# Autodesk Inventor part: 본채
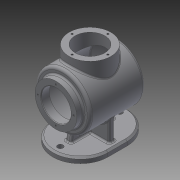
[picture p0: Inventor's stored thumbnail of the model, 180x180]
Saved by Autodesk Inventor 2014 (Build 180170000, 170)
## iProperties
Created: 2016-04
Part Number: 본채
Material: 일반
Document SubType Name: Modeling
Designer: basic
Density: 1 g/cm^3
Appearance: 기본값
Author: basic
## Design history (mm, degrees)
sketch "스케치6"
  geometry: L1 (-50, -67.5)-(50, -67.5); L2 (50, -67.5)-(50, 67.5); L3 (50, 67.5)-(-50, 67.5); L4 (-50, 67.5)-(-50, -67.5); L5 (-50, -67.5)-(50, 67.5); 2 further points
  constraints: 10 end point, 2 parallel, 1 coincident, 1 horizontal, 1 midpoint, 1 perpendicular
  dimensions: "d31" = 100 distance of L2.end L3.end; "d32" = 135 distance of L3.end L1.start
extrude "돌출3" join sketch "스케치6" distance "d34" = 10; taper "d35" = 0 deg
fillet "모깎기1" dims "d36" = 50
chamfer "모따기2" distance "d37" = 3; stored, may be unused: second distance "d38" = 2, angle "d39" = 45 deg
sketch "스케치7"
  geometry: L1 (64.5, 10)-(67.5, 7) reference; L2 (67.5, 7)-(67.5, 0) reference; L3 (67.5, 0)-(-67.5, 0) reference; L4 (-67.5, 0)-(-67.5, 7) reference; L5 (-67.5, 7)-(-64.5, 10) reference; L6 (-64.5, 10)-(64.5, 10) reference; L7 (-62, 79)-(60, 79); L8 (-62, 79)-(-62, 117); L9 (-62, 117)-(-50, 117); L10 (-50, 117)-(-50, 129); L11 (-62, 106)-(-47, 106); L12 (-47, 106)-(-47, 126); L13 (-47, 126)-(47.145, 126); L14 (-50, 129)-(49.087, 129); A1 r 120 centre (60, 79) between (-50, 126.958) and (-60, 79); A2 r 120 centre (-60, 79) between (60, 79) and (49.087, 129); A3 r 117 centre (-60, 79) between (57, 79) and (47.145, 126); 1 further point
  constraints: 16 end point, 6 point on circle, 4 point on line, 3 centre point, 3 parallel, 3 perpendicular, 1 coincident, 1 horizontal, 1 midpoint
  dimensions: "d40" = 122 distance of L7.end L7.start; "d41" = 79 distance between parallel lines of L3 L7; "d44" = 240 diameter of A1; "d46" = 3 radial gap between concentric circles of A2 A3; "d47" = 15 distance of L11.start L11.end; "d48" = 12 distance of L8.end L9.end; "d49" = 3 distance between parallel lines of L13 L14; "d50" = 50 distance between parallel lines of L7 L14; "d51" = 38 distance between parallel lines of L7 L9; "d52" = 27 distance between parallel lines of L7 L11; "d115" = 62 distance from line of point (0, 0) L8
revolve "회전3" sketch "스케치7" stored, may be unused: angle "d53" = 90 deg
sketch "스케치8" dims "d54" = 65
  geometry: L1 (0, 0)-(32.5, 0); C1 r 38 at (0, 0) reference; 2 further points
  constraints: 2 coincident, 2 end point, 1 horizontal, 1 horizontal alignment, 2 other
hole "구멍1" sketch "스케치8" at (32.5, 0) diameter "d55" = 3.242; stored, may be unused: countersink angle "d59" = 90 deg, drill point angle "d61" = 118 deg; dims "d56" = 8, "d57" = 4, "d58" = 2, "d60" = 10
node "작업 평면1"
sketch "스케치12"
  geometry: C1 r 5 at (0, -54); C2 r 5 at (0, 54); A1 r 47 centre (0, -17.5) between (-47, -17.5) and (47, -17.5) reference; A2 r 47 centre (0, 17.5) between (47, 17.5) and (-47, 17.5) reference; 1 further point
  constraints: 2 centre point, 2 vertical alignment
  dimensions: "d83" = 10 diameter of C1; "d84" = 10 diameter of C2; "d85" = 54 distance of point (0, 0) C1.centre; "d86" = 54 distance of C2.centre point (0, 0)
extrude "돌출6" cut sketch "스케치12" stored distance "d87" = 10; taper "d88" = 0 deg
fillet "모깎기2" dims "d89" = 2
fillet "모깎기3" dims "d90" = 5
chamfer "모따기3" distance "d91" = 1; stored, may be unused: second distance "d92" = 2, angle "d93" = 45 deg
sketch "스케치14"
  geometry: L1 (-50, 7)-(-47, 10) reference; L2 (-47, 10)-(47, 10) reference; L3 (47, 10)-(50, 7) reference; L4 (50, 7)-(50, 0) reference; L5 (50, 0)-(-50, 0) reference; L6 (-50, 0)-(-50, 7) reference; L7 (40, 10)-(40, 49); L8 (-40, 49)-(-40, 10); C1 r 47 at (0, 79) reference; A1 r 50 centre (0, 79) between (-40, 49) and (40, 49) reference; 1 further point
  constraints: 4 end point, 2 point on circle, 2 point on line, 1 parallel
  dimensions: "d99" = 40 distance from line of C1.centre L7; "d100" = 80 distance between parallel lines of L8 L7
extrude "돌출8" join sketch "스케치14" stored distance "d101" = 10; taper "d102" = 0 deg
sketch "스케치15"
  geometry: L1 (-51.026, 111.5)-(-52, 113.121) reference; L2 (-52, 113.121)-(-62, 113.121) reference; L3 (-62, 113.121)-(-62, 117) reference; L4 (-62, 117)-(-50, 117) reference; L5 (-50, 117)-(-50, 124) reference; L6 (-45, 129)-(45.83, 129) reference; L7 (45.83, 126)-(-45, 126) reference; L8 (-47, 124)-(-47, 106) reference; L9 (-47, 106)-(-61, 106) reference; L10 (-61, 106)-(-62, 107) reference; L11 (-62, 107)-(-62, 109.879) reference; L12 (-62, 109.879)-(-52, 109.879) reference; L13 (-52, 109.879)-(-51.026, 111.5) reference; L14 (49, 10)-(49, 0) reference; L15 (49, 0)-(-49, 0) reference; L16 (-49, 0)-(-49, 10) reference; L17 (-49, 10)-(-5, 10) reference; L18 (-5, 10)-(-5, 29) reference; L19 (-5, 29)-(-45, 29) reference; L20 (-50, 34)-(-50, 41) reference; L21 (-50, 41)-(-62, 41) reference; L22 (-62, 41)-(-62, 44.879) reference; L23 (-62, 44.879)-(-52, 44.879) reference; L24 (-52, 44.879)-(-51.026, 46.5) reference; L25 (-51.026, 46.5)-(-52, 48.121) reference; L26 (-52, 48.121)-(-62, 48.121) reference; L27 (-62, 48.121)-(-62, 51) reference; L28 (-62, 51)-(-61, 52) reference; L29 (-61, 52)-(-47, 52) reference; L30 (-47, 52)-(-47, 34) reference; L31 (-45, 32)-(45.83, 32) reference; L32 (45.83, 29)-(5, 29) reference; L33 (5, 29)-(5, 10) reference; L34 (5, 10)-(49, 10) reference; L35 (-67.5, 7)-(-64.5, 10) reference; L36 (-64.5, 10)-(-59, 10) reference; L37 (-59, 10)-(-59, 0) reference; L38 (-59, 0)-(-67.5, 0) reference; L39 (-67.5, 0)-(-67.5, 7) reference; L40 (64.5, 10)-(67.5, 7) reference; L41 (67.5, 7)-(67.5, 0) reference; L42 (67.5, 0)-(59, 0) reference; L43 (59, 0)-(59, 10) reference; L44 (59, 10)-(64.5, 10) reference; L45 (-36.65, 29)-(-40, 10); A1 r 5 centre (-45, 124) between (-45, 129) and (-50, 124) reference; A2 r 2 centre (-45, 124) between (-45, 126) and (-47, 124) reference; A3 r 5 centre (-45, 34) between (-50, 34) and (-45, 29) reference; A4 r 2 centre (-45, 34) between (-47, 34) and (-45, 32) reference; A5 r 2 centre (45.83, 34) between (45.83, 32) and (47.671, 33.217) reference; A6 r 117 centre (-60, 79) between (47.671, 33.217) and (47.671, 124.783) reference; A7 r 2 centre (45.83, 124) between (47.671, 124.783) and (45.83, 126) reference; A8 r 5 centre (45.83, 124) between (50.431, 125.957) and (45.83, 129) reference; A9 r 120 centre (-60, 79) between (50.431, 32.043) and (50.431, 125.957) reference; A10 r 5 centre (45.83, 34) between (45.83, 29) and (50.431, 32.043) reference; 1 further point
  constraints: 2 end point, 2 point on line
  dimensions: "d105" = 40 horizontal distance of point (0, 0) L45.end; "d106" = 100 deg angle of L17 L45
feature "리브1" sketch "스케치15" dims "d107" = 1, "d108" = 10, "d109" = 0, "d110" = 0, "d111" = 1, "d112" = 1
sketch "스케치16"
  geometry: L1 (38, -62)-(-38, -62) reference; C1 r 38 at (0, 0); 1 further point
  constraints: 2 coincident, 1 centre point
  dimensions: "d113" = 76 diameter of C1
extrude "돌출9" join sketch "스케치16" stored distance "d116" = 10; taper "d117" = 0 deg
sketch "스케치17"
  geometry: C1 r 38 at (0, 0) reference; C2 r 27 at (0, 0)
  constraints: 1 centre point, 1 coincident
  dimensions: "d118" = 54 diameter of C2
extrude "돌출10" cut sketch "스케치17" stored distance "d119" = 10; taper "d120" = 0 deg
sketch "스케치18" dims "d121" = 65
  geometry: L1 (0, 0)-(-32.5, 0); C1 r 38 at (0, 0) reference; 1 further point
  constraints: 2 coincident, 2 end point, 1 horizontal, 1 horizontal alignment, 2 other
hole "구멍3" sketch "스케치18" at (-32.5, 0) diameter "d122" = 3.242; stored, may be unused: countersink angle "d126" = 90 deg, drill point angle "d128" = 118 deg; dims "d123" = 8, "d124" = 4, "d125" = 2, "d127" = 10
fillet "모깎기4" dims "d132" = 3
fillet "모깎기5" dims "d133" = 3
node "작업 평면3"
sketch "스케치19"
  geometry: L1 (26.339, -79)-(-26.339, -79) reference; L2 (-26.339, -79)-(-26.339, -72) reference; L3 (-20.069, -69)-(20.069, -69) reference; L4 (26.339, -72)-(26.339, -79) reference; 3 further points
  constraints: 1 coincident, 3 other
feature "엠보싱1" sketch "스케치19" dims "d31" = 100, "d32" = 135, "d40" = 122, "d41" = 79, "d44" = 240, "d46" = 3, "d47" = 15, "d48" = 12, "d49" = 3, "d50" = 50, "d51" = 38, "d52" = 27, "d115" = 62, "d134" = 0.5, "d135" = 0
node "솔리드2"
pattern_circular "원형 패턴1" dims angle "d63" = 360 deg
pattern_circular "원형 패턴3" dims angle "d130" = 360 deg
mirror "대칭1"
node "절단 모서리 투영2"
node "절단 모서리 투영4"
node "절단 모서리 투영5"
node "절단 모서리 투영6"
other parameters: "d65" = 144
